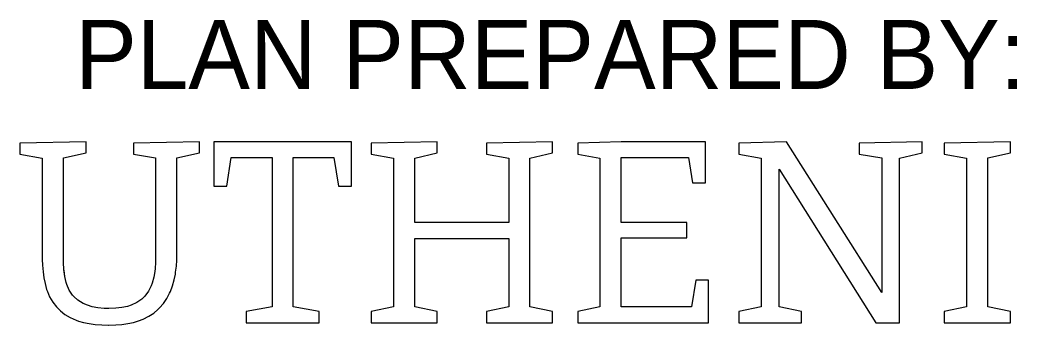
# Model space of a CAD drawing. Extents: x 0 to 34, y 0 to 22.
# Drawn here: x 3.993 to 6.013, y 1.074 to 1.693 of the extents above; entities that cross this region are included whole.
import ezdxf

# ---------------------------------------------------------------- set-up
doc = ezdxf.new("R2010")
doc.units = 0
doc.layers.add('SH_Logo', color=7, linetype='Continuous')
doc.layers.add('SH_Text', color=7, linetype='Continuous')

msp = doc.modelspace()

# ---------------------------------------------------------------- linework, layer by layer
at = {"layer": 'SH_Logo'}
for points in [[(4.1736, 1.1079), (4.1641, 1.1082), (4.1512, 1.1094), (4.1398, 1.1116), (4.1299, 1.1148), (4.1214, 1.1184), (4.1109, 1.1246), (4.1026, 1.1322), (4.0999, 1.1353), (4.093, 1.1452), (4.0885, 1.1564), (4.0869, 1.1608), (4.0842, 1.1725), (4.0827, 1.1847), (4.0824, 1.1877), (4.0818, 1.2002), (4.0816, 1.212), (4.0816, 1.4131), (4.1272, 1.4235), (4.1272, 1.4461), (3.9933, 1.4434), (3.9933, 1.4209), (4.0384, 1.413), (4.0384, 1.212), (4.0386, 1.2072), (4.0391, 1.1955), (4.0401, 1.1821), (4.0415, 1.1704), (4.0441, 1.1585), (4.0474, 1.1464), (4.0488, 1.1423), (4.0535, 1.1315), (4.0597, 1.121), (4.0673, 1.1111), (4.0675, 1.111), (4.0754, 1.1031), (4.0845, 1.0959), (4.0951, 1.0897), (4.1073, 1.0844), (4.112, 1.0825), (4.1223, 1.0797), (4.1336, 1.0774), (4.1458, 1.0757), (4.159, 1.0746), (4.173, 1.0743), (4.1736, 1.0743), (4.1873, 1.0746), (4.2, 1.0757), (4.212, 1.0774), (4.2231, 1.0798), (4.2335, 1.0827), (4.2432, 1.0865), (4.2543, 1.0921), (4.2642, 1.0985), (4.2728, 1.106), (4.276, 1.1091), (4.2841, 1.1184), (4.2909, 1.1284), (4.2965, 1.1391), (4.2982, 1.1427), (4.3023, 1.1541), (4.3057, 1.1658), (4.3081, 1.1778), (4.3085, 1.1815), (4.3101, 1.1938), (4.3108, 1.206), (4.3111, 1.2178), (4.3111, 1.4133), (4.3569, 1.4235), (4.3569, 1.4461), (4.223, 1.4434), (4.223, 1.4209), (4.2681, 1.4133), (4.2681, 1.2178), (4.2681, 1.2134), (4.2678, 1.2013), (4.2671, 1.1889), (4.2666, 1.1832), (4.2645, 1.1712), (4.2613, 1.1595), (4.2591, 1.1538), (4.2537, 1.143), (4.2465, 1.1332), (4.2401, 1.1271), (4.2303, 1.1204), (4.2187, 1.1148), (4.211, 1.1123), (4.1997, 1.1099), (4.1873, 1.1085)], [(4.0816, 1.4131), (4.1272, 1.4235), (4.1272, 1.4461), (3.9933, 1.4434), (3.9933, 1.4209), (4.0384, 1.413), (4.0384, 1.212), (4.0386, 1.2072), (4.0391, 1.1955), (4.0401, 1.1821), (4.0415, 1.1704), (4.0441, 1.1585), (4.0474, 1.1464), (4.0488, 1.1423), (4.0535, 1.1315), (4.0597, 1.121), (4.0673, 1.1111), (4.0754, 1.1031), (4.0845, 1.0959), (4.0951, 1.0897), (4.1073, 1.0844), (4.112, 1.0825), (4.1223, 1.0797), (4.1336, 1.0774), (4.1458, 1.0757), (4.159, 1.0746), (4.173, 1.0743), (4.1736, 1.0743), (4.1873, 1.0746), (4.2, 1.0757), (4.212, 1.0774), (4.2231, 1.0798), (4.2335, 1.0827), (4.2432, 1.0865), (4.2543, 1.0921), (4.2642, 1.0985), (4.2728, 1.106), (4.276, 1.1091), (4.2841, 1.1184), (4.2909, 1.1284), (4.2965, 1.1391), (4.2982, 1.1427), (4.3023, 1.1541), (4.3057, 1.1658), (4.3081, 1.1778), (4.3085, 1.1815), (4.3101, 1.1938), (4.3108, 1.206), (4.3111, 1.2178), (4.3111, 1.4133), (4.3569, 1.4235), (4.3569, 1.4461), (4.223, 1.4434), (4.223, 1.4209), (4.2681, 1.4133), (4.2681, 1.2134), (4.2678, 1.2013), (4.2671, 1.1889), (4.2666, 1.1832), (4.2645, 1.1712), (4.2613, 1.1595), (4.2591, 1.1538), (4.2537, 1.143), (4.2465, 1.1332), (4.2401, 1.1271), (4.2303, 1.1204), (4.2187, 1.1148), (4.211, 1.1123), (4.1997, 1.1099), (4.1873, 1.1085), (4.1736, 1.1079), (4.1641, 1.1082), (4.1512, 1.1094), (4.1398, 1.1116), (4.1299, 1.1148), (4.1214, 1.1184), (4.1109, 1.1246), (4.1026, 1.1322), (4.0999, 1.1353), (4.093, 1.1452), (4.0885, 1.1564), (4.0869, 1.1608), (4.0842, 1.1725), (4.0824, 1.1867), (4.0818, 1.2002), (4.0816, 1.212)], [(4.5466, 1.4141), (4.6293, 1.4141), (4.6385, 1.3561), (4.6648, 1.3561), (4.6648, 1.4461), (4.3858, 1.4461), (4.3858, 1.3561), (4.4121, 1.3561), (4.4212, 1.4141), (4.504, 1.4141), (4.504, 1.1113), (4.4514, 1.1017), (4.4514, 1.079), (4.5992, 1.079), (4.5992, 1.1017), (4.5466, 1.1113)], [(4.5466, 1.4141), (4.6293, 1.4141), (4.6385, 1.3561), (4.6648, 1.3561), (4.6648, 1.4461), (4.3858, 1.4461), (4.3858, 1.3561), (4.4121, 1.3561), (4.4212, 1.4141), (4.504, 1.4141), (4.504, 1.1113), (4.4514, 1.1017), (4.4514, 1.079), (4.5992, 1.079), (4.5992, 1.1017), (4.5466, 1.1113)], [(5.072, 1.4461), (4.9381, 1.4434), (4.9381, 1.4209), (4.9833, 1.4128), (4.9833, 1.282), (4.7931, 1.282), (4.7931, 1.413), (4.8387, 1.4235), (4.8387, 1.4461), (4.7048, 1.4434), (4.7048, 1.4209), (4.75, 1.4128), (4.75, 1.1113), (4.7048, 1.1017), (4.7048, 1.079), (4.8387, 1.079), (4.8387, 1.1017), (4.7931, 1.1113), (4.7931, 1.2499), (4.9833, 1.2499), (4.9833, 1.1113), (4.9381, 1.1017), (4.9381, 1.079), (5.072, 1.079), (5.072, 1.1017), (5.0263, 1.1113), (5.0263, 1.413), (5.072, 1.4235)], [(5.0263, 1.413), (5.072, 1.4235), (5.072, 1.4461), (4.9381, 1.4434), (4.9381, 1.4209), (4.9833, 1.4128), (4.9833, 1.282), (4.7931, 1.282), (4.7931, 1.413), (4.8387, 1.4235), (4.8387, 1.4461), (4.7048, 1.4434), (4.7048, 1.4209), (4.75, 1.4128), (4.75, 1.1113), (4.7048, 1.1017), (4.7048, 1.079), (4.8387, 1.079), (4.8387, 1.1017), (4.7931, 1.1113), (4.7931, 1.2499), (4.9833, 1.2499), (4.9833, 1.1113), (4.9381, 1.1017), (4.9381, 1.079), (5.072, 1.079), (5.072, 1.1017), (5.0263, 1.1113)], [(5.3883, 1.1652), (5.3622, 1.1652), (5.3538, 1.1111), (5.2113, 1.1111), (5.2113, 1.251), (5.3438, 1.251), (5.3438, 1.2826), (5.2113, 1.2826), (5.2113, 1.4141), (5.3475, 1.4141), (5.3558, 1.363), (5.3821, 1.363), (5.3821, 1.4461), (5.2108, 1.4461), (5.1231, 1.4434), (5.1231, 1.4209), (5.1682, 1.4127), (5.1682, 1.1113), (5.1231, 1.1017), (5.1231, 1.079), (5.3883, 1.079)], [(5.3438, 1.2826), (5.2113, 1.2826), (5.2113, 1.4141), (5.3475, 1.4141), (5.3558, 1.363), (5.3821, 1.363), (5.3821, 1.4461), (5.2108, 1.4461), (5.1231, 1.4434), (5.1231, 1.4209), (5.1682, 1.4127), (5.1682, 1.1113), (5.1231, 1.1017), (5.1231, 1.079), (5.3883, 1.079), (5.3883, 1.1652), (5.3622, 1.1652), (5.3538, 1.1111), (5.2113, 1.1111), (5.2113, 1.251), (5.3438, 1.251)], [(5.4946, 1.4128), (5.4946, 1.1111), (5.4493, 1.1017), (5.4493, 1.079), (5.5765, 1.079), (5.5765, 1.1017), (5.5314, 1.1111), (5.5314, 1.3903), (5.7268, 1.079), (5.7752, 1.079), (5.7752, 1.413), (5.8209, 1.4235), (5.8209, 1.4461), (5.6933, 1.4434), (5.6933, 1.4209), (5.7389, 1.4131), (5.7389, 1.1402), (5.5461, 1.4461), (5.4493, 1.4434), (5.4493, 1.4209)], [(5.5314, 1.3903), (5.7268, 1.079), (5.7752, 1.079), (5.7752, 1.413), (5.8209, 1.4235), (5.8209, 1.4461), (5.6933, 1.4434), (5.6933, 1.4209), (5.7389, 1.4131), (5.7389, 1.1402), (5.5461, 1.4461), (5.4493, 1.4434), (5.4493, 1.4209), (5.4946, 1.4128), (5.4946, 1.1111), (5.4493, 1.1017), (5.4493, 1.079), (5.5765, 1.079), (5.5765, 1.1017), (5.5314, 1.1111)], [(5.9995, 1.4461), (5.8655, 1.4434), (5.8655, 1.4209), (5.9108, 1.4127), (5.9108, 1.111), (5.8655, 1.1017), (5.8655, 1.079), (5.9995, 1.079), (5.9995, 1.1017), (5.9538, 1.111), (5.9538, 1.4131), (5.9995, 1.4235)], [(5.9538, 1.4131), (5.9995, 1.4235), (5.9995, 1.4461), (5.8655, 1.4434), (5.8655, 1.4209), (5.9108, 1.4127), (5.9108, 1.111), (5.8655, 1.1017), (5.8655, 1.079), (5.9995, 1.079), (5.9995, 1.1017), (5.9538, 1.111)]]:
    msp.add_lwpolyline(points, close=True, dxfattribs=at)
for points in [[(4.6293, 1.4141), (4.6385, 1.3561), (4.6648, 1.3561), (4.6648, 1.4461)], [(4.504, 1.4141), (4.504, 1.1113), (4.4514, 1.1017), (4.4514, 1.079), (4.5992, 1.079), (4.5992, 1.1017), (4.5466, 1.1113), (4.5466, 1.4141)]]:
    msp.add_lwpolyline(points, dxfattribs=at)

# ---------------------------------------------------------------- texts
at = {"layer": 'SH_Text'}
msp.add_text('PLAN PREPARED BY:', height=0.14, dxfattribs=at).set_placement((4.1053, 1.553))

doc.saveas('drawing.dxf')
